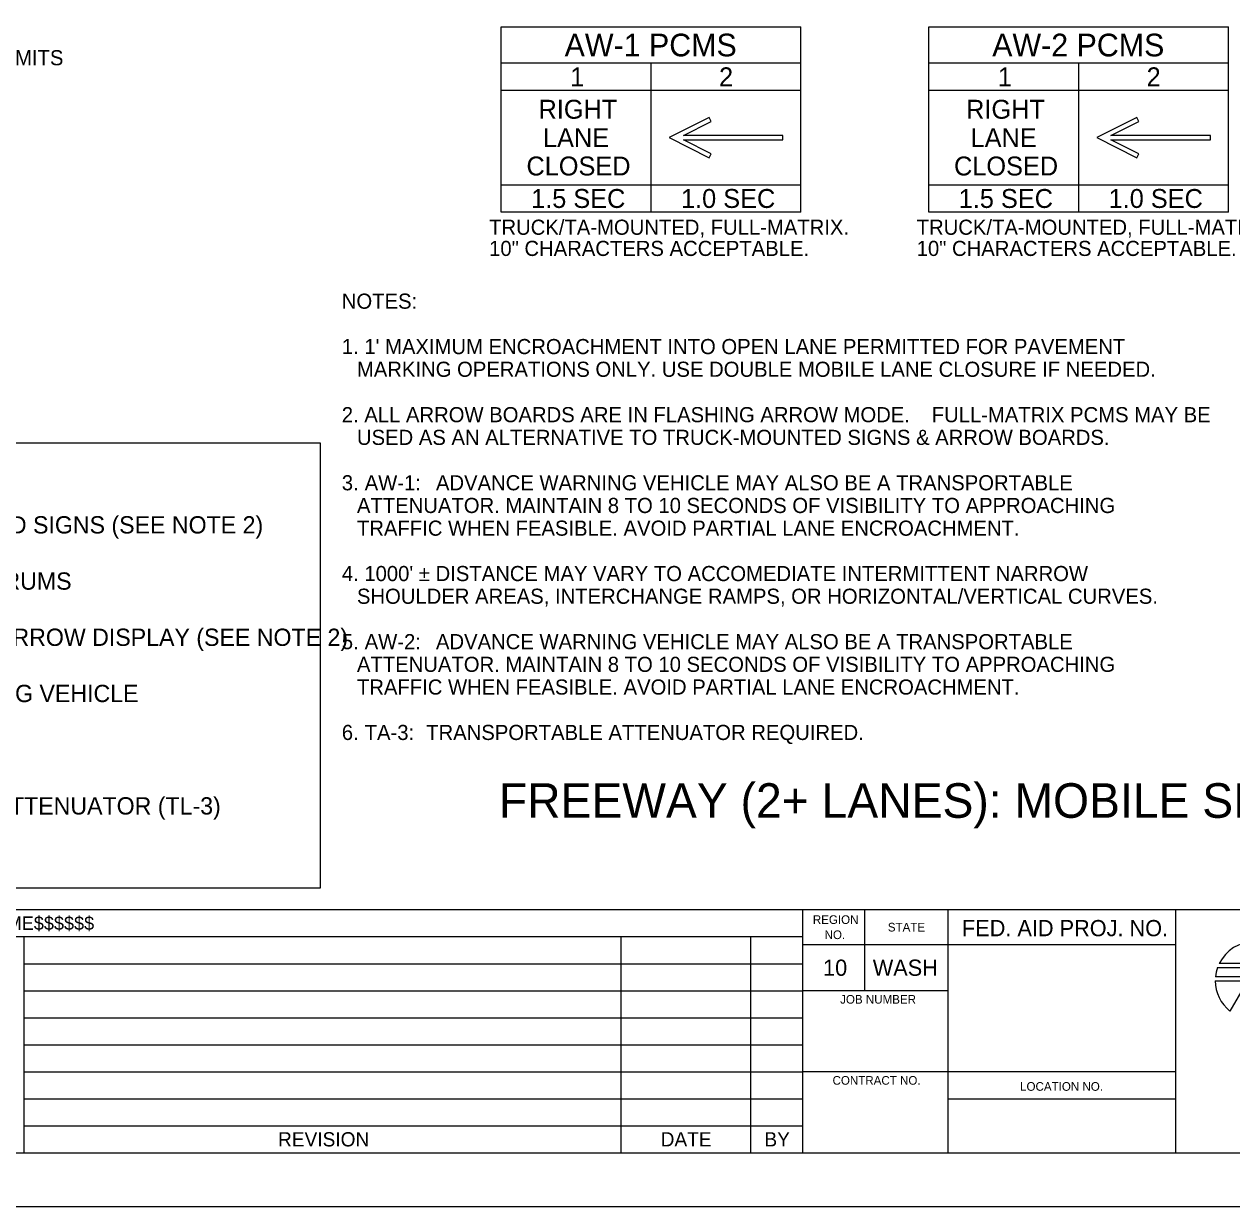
# Model space of a CAD drawing. Extents: x 0 to 17, y 0 to 11.
# Drawn here: x 2.92 to 8.5, y 0 to 5.47 of the extents above; entities that cross this region are included whole.
import ezdxf

# ---------------------------------------------------------------- set-up
doc = ezdxf.new("R2010")
doc.units = 0
for name, color, linetype in [('SH_GI_Logo_WSDOT', 7, 'Continuous'), ('SH_GI_PlotLimits', 7, 'Continuous'), ('SH_GI_SheetBorder1', 7, 'Continuous'), ('SH_GI_SheetBorder2', 7, 'Continuous'), ('SH_GI_SheetBorder3', 7, 'Continuous'), ('SH_GI_SheetTextInCells', 7, 'Continuous'), ('SH_GI_TitleBlockText', 7, 'Continuous'), ('TR_WZ_PortableChangeMessageSign', 7, 'Continuous'), ('TR_WZ_WorkZoneTextCurrent', 7, 'Continuous')]:
    doc.layers.add(name, color=color, linetype=linetype)

msp = doc.modelspace()

# ---------------------------------------------------------------- linework, layer by layer
at = {"layer": 'SH_GI_Logo_WSDOT'}
for p, q in [((8.6489, 1.1258), (8.4454, 1.1258)), ((8.59, 1.0643), (8.4278, 1.0643)), ((8.4377, 1.1078), (8.6354, 1.1078)), ((8.4269, 1.0463), (8.5657, 1.0463)), ((8.5709, 1.0373), (8.4948, 0.9054))]:
    msp.add_line(p, q, dxfattribs=at)
for start, end in [(26.2103, 153.7897), (160.0216, 174.2608), (180, 231.4963)]:
    msp.add_arc((8.6069, 1.0463), 0.18, start, end, dxfattribs=at)
at = {"layer": 'SH_GI_PlotLimits'}
msp.add_lwpolyline([(0, 11), (17, 11), (17, 0), (0, 0)], close=True, dxfattribs=at)
at = {"layer": 'SH_GI_SheetBorder1'}
for p, q in [((8.245, 1.2125), (6.52, 1.2125)), ((2.92, 1.125), (6.52, 1.125)), ((2.92, 1), (6.52, 1)), ((2.92, 0.875), (6.52, 0.875)), ((2.92, 0.75), (6.52, 0.75)), ((2.92, 0.625), (6.52, 0.625)), ((2.92, 0.5), (6.52, 0.5)), ((7.1913, 0.5), (8.245, 0.5))]:
    msp.add_line(p, q, dxfattribs=at)
at = {"layer": 'SH_GI_SheetBorder2'}
for p, q in [((6.8073, 1), (6.8073, 1.375)), ((7.1913, 1), (6.52, 1)), ((8.245, 0.625), (6.52, 0.625)), ((2.92, 0.375), (6.52, 0.375))]:
    msp.add_line(p, q, dxfattribs=at)
at = {"layer": 'SH_GI_SheetBorder3'}
for p, q in [((1, 1.375), (16.75, 1.375)), ((6.52, 0.25), (6.52, 1.375)), ((7.1913, 0.25), (7.1913, 1.375)), ((8.245, 0.25), (8.245, 1.375)), ((1, 1.25), (6.52, 1.25)), ((2.92, 0.25), (2.92, 1.25)), ((5.68, 0.25), (5.68, 1.25)), ((6.28, 0.25), (6.28, 1.25)), ((1, 0.25), (16.75, 0.25))]:
    msp.add_line(p, q, dxfattribs=at)
at = {"layer": 'TR_WZ_PortableChangeMessageSign'}
for p, q in [((5.1255, 5.4586), (6.5115, 5.4586)), ((5.1255, 4.6018), (5.1255, 5.4586)), ((6.5115, 4.6018), (6.5115, 5.4586)), ((7.1024, 5.4586), (8.4884, 5.4586)), ((7.1024, 4.6018), (7.1024, 5.4586)), ((8.4884, 4.6018), (8.4884, 5.4586)), ((6.5115, 5.2906), (5.1255, 5.2906)), ((5.8185, 4.6018), (5.8185, 5.2906)), ((8.4884, 5.2906), (7.1024, 5.2906)), ((7.7954, 4.6018), (7.7954, 5.2906)), ((5.8185, 5.1646), (5.1255, 5.1646)), ((6.5115, 5.1646), (5.8185, 5.1646)), ((7.7954, 5.1646), (7.1024, 5.1646)), ((8.4884, 5.1646), (7.7954, 5.1646)), ((6.0865, 5.0395), (5.9025, 4.9462)), ((8.0634, 5.0395), (7.8794, 4.9462)), ((6.4275, 4.9567), (5.9677, 4.9567)), ((5.9677, 4.9357), (6.4275, 4.9357)), ((6.4275, 4.9357), (6.4275, 4.9567)), ((8.4044, 4.9567), (7.9445, 4.9567)), ((7.9445, 4.9357), (8.4044, 4.9357)), ((8.4044, 4.9357), (8.4044, 4.9567)), ((5.1255, 4.7278), (5.8185, 4.7278)), ((5.8185, 4.7278), (6.5115, 4.7278)), ((7.1024, 4.7278), (7.7954, 4.7278)), ((7.7954, 4.7278), (8.4884, 4.7278)), ((6.5115, 4.6018), (5.1255, 4.6018)), ((8.4884, 4.6018), (7.1024, 4.6018))]:
    msp.add_line(p, q, dxfattribs=at)
for points in [[(5.9677, 4.9567), (6.0959, 5.0208), (6.0912, 5.0302), (6.0865, 5.0395)], [(7.9445, 4.9567), (8.0728, 5.0208), (8.0681, 5.0302), (8.0634, 5.0395)], [(5.9025, 4.9462), (6.0865, 4.8528), (6.0912, 4.8622), (6.0959, 4.8715), (5.9677, 4.9357)], [(7.8794, 4.9462), (8.0634, 4.8528), (8.0681, 4.8622), (8.0728, 4.8715), (7.9445, 4.9357)]]:
    msp.add_lwpolyline(points, dxfattribs=at)
at = {"layer": 'TR_WZ_WorkZoneTextCurrent'}
msp.add_lwpolyline([(1.1, 3.535), (4.2886, 3.535), (4.2886, 1.475), (1.1, 1.475)], close=True, dxfattribs=at)

# ---------------------------------------------------------------- texts
at = {"layer": 'SH_GI_SheetTextInCells'}
for s, height, p in [('REGION', 0.04, (6.5662, 1.3088)), ('STATE', 0.04, (6.9129, 1.2738)), ('FED. AID PROJ. NO.', 0.075, (7.2558, 1.252)), ('NO.', 0.04, (6.6206, 1.2387)), ('10', 0.075, (6.6136, 1.0688)), ('WASH', 0.075, (6.8434, 1.0688)), ('JOB NUMBER', 0.04, (6.6925, 0.94)), ('CONTRACT NO.', 0.04, (6.6574, 0.565)), ('LOCATION NO.', 0.04, (7.5244, 0.537)), ('REVISION', 0.066, (4.0938, 0.2795)), ('DATE', 0.066, (5.8627, 0.2795)), ('BY', 0.066, (6.3424, 0.2795))]:
    msp.add_text(s, height=height, dxfattribs=at).set_placement(p)
at = {"layer": 'SH_GI_TitleBlockText'}
msp.add_text('$$$$$$$$DESIGNFILENAME$$$$$$', height=0.0625, dxfattribs=at).set_placement((1.8545, 1.2812))
at = {"layer": 'TR_WZ_PortableChangeMessageSign'}
for s, height, p in [('AW-1 PCMS', 0.105, (5.4187, 5.3221)), ('AW-2 PCMS', 0.105, (7.3956, 5.3221)), ('MOBILE LANE CLOSURE OPERATION LIMITS ', 0.07, (1.0938, 5.2809)), ('1', 0.0875, (5.4446, 5.1838)), ('2', 0.0875, (6.1326, 5.1838)), ('1', 0.0875, (7.4215, 5.1838)), ('2', 0.0875, (8.1094, 5.1838)), ('RIGHT', 0.0875, (5.2981, 5.0337)), ('RIGHT', 0.0875, (7.2749, 5.0337)), ('LANE', 0.0875, (5.3188, 4.9024)), ('LANE', 0.0875, (7.2956, 4.9024)), ('CLOSED', 0.0875, (5.2423, 4.7712)), ('CLOSED', 0.0875, (7.2191, 4.7712)), ('1.5 SEC', 0.0875, (5.2638, 4.621)), ('1.0 SEC', 0.0875, (5.9568, 4.621)), ('1.5 SEC', 0.0875, (7.2407, 4.621)), ('1.0 SEC', 0.0875, (7.9337, 4.621)), ('TRUCK/TA-MOUNTED, FULL-MATRIX.', 0.07, (5.0696, 4.4968)), ('TRUCK/TA-MOUNTED, FULL-MATRIX.', 0.07, (7.0464, 4.4968)), ('10" CHARACTERS ACCEPTABLE.', 0.07, (5.0696, 4.3988)), ('10" CHARACTERS ACCEPTABLE.', 0.07, (7.0464, 4.3988))]:
    msp.add_text(s, height=height, rotation=360, dxfattribs=at).set_placement(p)
at = {"layer": 'TR_WZ_WorkZoneTextCurrent'}
for s, height, p in [('NOTES:', 0.07, (4.3886, 4.1547)), ("1. 1' MAXIMUM ENCROACHMENT INTO OPEN LANE PERMITTED FOR PAVEMENT ", 0.07, (4.3886, 3.9447)), ('MARKING OPERATIONS ONLY. USE DOUBLE MOBILE LANE CLOSURE IF NEEDED.', 0.07, (4.4586, 3.8397)), ('2. ALL ARROW BOARDS ARE IN FLASHING ARROW MODE. ', 0.07, (4.3886, 3.6297)), ('FULL-MATRIX PCMS MAY BE ', 0.07, (7.1158, 3.6297)), ('USED AS AN ALTERNATIVE TO TRUCK-MOUNTED SIGNS & ARROW BOARDS.', 0.07, (4.4586, 3.5247)), ('3. ', 0.07, (4.3886, 3.3147)), ('AW-1:', 0.07, (4.4943, 3.3147)), (' ADVANCE WARNING VEHICLE MAY ALSO BE A TRANSPORTABLE ', 0.07, (4.7978, 3.3147)), ('ATTENUATOR. MAINTAIN 8 TO 10 SECONDS OF VISIBILITY TO APPROACHING ', 0.07, (4.4586, 3.2097)), ('TRUCK/TA-MOUNTED SIGNS (SEE NOTE 2)', 0.08, (1.82, 3.115)), ('TRAFFIC WHEN FEASIBLE. AVOID PARTIAL LANE ENCROACHMENT.', 0.07, (4.4586, 3.1047)), ("4. 1000' ± DISTANCE MAY VARY TO ACCOMEDIATE INTERMITTENT NARROW ", 0.07, (4.3886, 2.8947)), ('TRAFFIC SAFETY DRUMS', 0.08, (1.82, 2.855)), ('SHOULDER AREAS, INTERCHANGE RAMPS, OR HORIZONTAL/VERTICAL CURVES.', 0.07, (4.4586, 2.7897)), ('TRUCK-MOUNTED ARROW DISPLAY (SEE NOTE 2)', 0.08, (1.82, 2.595)), ('5. ', 0.07, (4.3886, 2.5797)), ('AW-2:', 0.07, (4.4943, 2.5797)), (' ADVANCE WARNING VEHICLE MAY ALSO BE A TRANSPORTABLE ', 0.07, (4.7978, 2.5797)), ('ATTENUATOR. MAINTAIN 8 TO 10 SECONDS OF VISIBILITY TO APPROACHING ', 0.07, (4.4586, 2.4747)), ('ADVANCED WARNING VEHICLE', 0.08, (1.82, 2.335)), ('TRAFFIC WHEN FEASIBLE. AVOID PARTIAL LANE ENCROACHMENT.', 0.07, (4.4586, 2.3697)), ('6. ', 0.07, (4.3886, 2.1597)), ('TA-3:', 0.07, (4.4943, 2.1597)), (' TRANSPORTABLE ATTENUATOR REQUIRED.', 0.07, (4.7527, 2.1597)), ('FREEWAY (2+ LANES): MOBILE SINGLE RIGHT LANE CLOSURE FOR PAVEMENT MARKING OPERATIONS', 0.16, (5.1148, 1.7997)), ('TRANSPORTABLE ATTENUATOR (TL-3)', 0.08, (1.82, 1.815))]:
    msp.add_text(s, height=height, rotation=360, dxfattribs=at).set_placement(p)

doc.saveas('drawing.dxf')
